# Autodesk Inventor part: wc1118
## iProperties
Shininess: 64.0
Length Units: 11272
Angle Units: 11279
Time Units: 11290
Mass Units: 11286
Length Display Precision: 3
Angle Display Precision: 2
Compacted: True
Part Number: wc1118
Document SubType Name: Modeling
Created: 2004-08
Designer: John Blackburn
Manufacturer: Standard
Standards Organization: Custom
Material: Phenolic
Density: 0.0
Volumn: 0.0
Area: 0.0
PropertySet Name: Model Information
Control State: 0
Master: False
Checked Out: False
Author: John Blackburn
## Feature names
1. Base1
